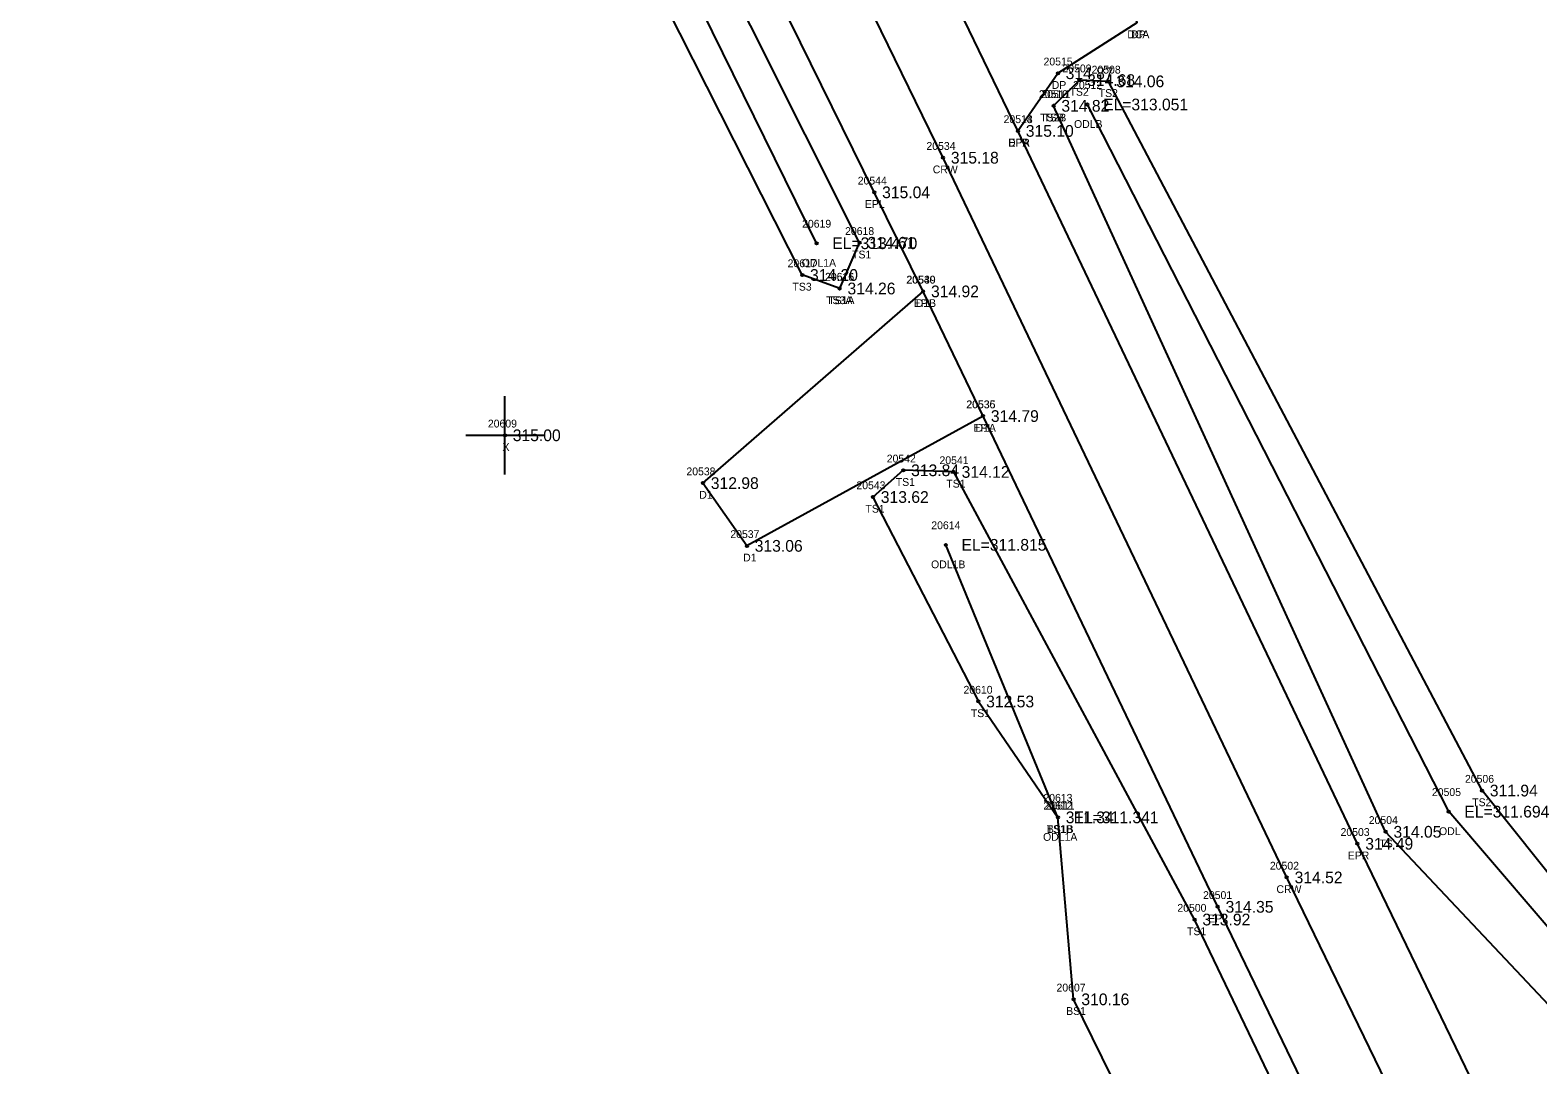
# Model space of a CAD drawing. Extents: x 1865771 to 1866867, y 910387 to 913581.
# Drawn here: x 1866027.9 to 1866220.8, y 911460.4 to 911592.8 of the extents above; entities that cross this region are included whole.
import ezdxf

# ---------------------------------------------------------------- set-up
doc = ezdxf.new("R2010")
doc.units = 0
for name, color, linetype in [('RD_DTM_BkLn1', 7, 'Continuous'), ('RD_DTM_BkLn2', 7, 'Continuous'), ('RD_DTM_BkLn_txCode', 7, 'Continuous'), ('RD_EX_Conc_txCode', 7, 'Continuous'), ('RD_EX_Driveway', 7, 'Continuous'), ('RD_EX_Driveway_txCode', 7, 'Continuous'), ('RD_EX_H2O', 7, 'Continuous'), ('RD_EX_H2O_txCode', 7, 'Continuous'), ('RD_EX_Misc', 7, 'Continuous'), ('RD_EX_Misc_txCode', 7, 'Continuous'), ('RD_EX_Road', 7, 'Continuous'), ('RD_EX_Road_txCode', 7, 'Continuous'), ('RD_EX_TX_Driveway_ELEV', 7, 'Continuous'), ('RD_EX_TX_H2O_ELEV', 7, 'Continuous'), ('RD_EX_TX_Misc_ELEV', 7, 'Continuous'), ('RD_EX_TX_Road_ELEV', 7, 'Continuous'), ('RD_HC_Survey_ELEV', 7, 'Continuous'), ('RD_HC_Survey_txCode', 7, 'Continuous'), ('RD_SMD_Locator', 7, 'Continuous')]:
    doc.layers.add(name, color=color, linetype=linetype)

msp = doc.modelspace()

# ---------------------------------------------------------------- linework, layer by layer
at = {"layer": 'RD_DTM_BkLn1'}
msp.add_lwpolyline([(1866367.09, 911115.22), (1866321.52, 911209.15), (1866277.71, 911299.75), (1866233.16, 911392.74), (1866188.7, 911484.36), (1866144.72, 911576.48), (1866098.88, 911670.46), (1866050.89, 911769.85), (1866036.73, 911799.27)], dxfattribs=at)
at = {"layer": 'RD_DTM_BkLn2'}
for points in [[(1866131.5, 911559.74), (1866126.7, 911561.47), (1866077.95, 911657.88), (1866039.91, 911695.55), (1866043.68, 911699.99)], [(1866131.5, 911559.74), (1866134.05, 911565.59), (1866085.26, 911662.93), (1866043.68, 911699.99)], [(1866228.56, 911467.21), (1866232.27, 911472.22), (1866213.68, 911495.48), (1866165.89, 911586.25), (1866162.16, 911586.41), (1866158.86, 911583.12)], [(1866228.56, 911467.21), (1866222.94, 911467.23), (1866201.35, 911490.2), (1866158.86, 911583.12)], [(1866355.6, 911109.43), (1866349.51, 911111.22), (1866350.92, 911120.01), (1866309.89, 911202.06), (1866265.74, 911294.86), (1866220.97, 911386.97), (1866176.9, 911478.97), (1866146.1, 911536.26), (1866139.64, 911536.47), (1866135.76, 911533.05), (1866149.24, 911506.88), (1866159.42, 911492.05)], [(1866341.34, 911101.29), (1866293.82, 911197.85), (1866256.26, 911274.61), (1866200.37, 911389.5), (1866161.42, 911468.76), (1866159.42, 911492.05)]]:
    msp.add_lwpolyline(points, dxfattribs=at)
at = {"layer": 'RD_EX_Driveway'}
for points in [[(1866154.31, 911579.91), (1866159.41, 911587.29), (1866169.57, 911593.77), (1866165.13, 911606.88), (1866152.14, 911603.8), (1866143.08, 911603.17)], [(1866149.84, 911543.41), (1866119.63, 911526.8), (1866114.01, 911534.83), (1866142.18, 911559.37)]]:
    msp.add_lwpolyline(points, dxfattribs=at)
at = {"layer": 'RD_EX_H2O'}
msp.add_line((1866159.42, 911492.05), (1866145.08, 911526.93), dxfattribs=at)
for points in [[(1866128.55, 911565.53), (1866081.91, 911660.36), (1866044.12, 911695.93)], [(1866226.46, 911472.93), (1866209.42, 911492.78), (1866163.2, 911583.29)]]:
    msp.add_lwpolyline(points, dxfattribs=at)
at = {"layer": 'RD_EX_Misc'}
for p, q in [((1866088.67, 911535.95), (1866088.67, 911545.95)), ((1866083.67, 911540.95), (1866093.67, 911540.95))]:
    msp.add_line(p, q, dxfattribs=at)
at = {"layer": 'RD_EX_Road'}
for points in [[(1866367.09, 911115.22), (1866376.17, 911119.76), (1866330.4, 911213.7), (1866286.92, 911304.16), (1866242.4, 911396.3), (1866197.74, 911488.67), (1866154.31, 911579.91), (1866143.08, 911603.17), (1866108.16, 911674.25), (1866059.64, 911774.84), (1866048.38, 911798.67), (1866045.99, 911803.62)], [(1866367.09, 911115.22), (1866357.99, 911110.97), (1866313.12, 911203.44), (1866268.86, 911295.9), (1866224.24, 911388.66), (1866179.87, 911480.6), (1866149.84, 911543.41), (1866142.18, 911559.37), (1866135.93, 911572.05), (1866096.83, 911651.51), (1866089.65, 911665.46), (1866062.87, 911720.39), (1866042.14, 911765.69), (1866027.93, 911795.04)]]:
    msp.add_lwpolyline(points, dxfattribs=at)
at = {"layer": 'RD_SMD_Locator'}
for centre in [(1866159.41, 911587.29), (1866162.16, 911586.41), (1866165.89, 911586.25), (1866158.86, 911583.12), (1866158.86, 911583.12), (1866163.2, 911583.29), (1866154.31, 911579.91), (1866154.31, 911579.91), (1866144.72, 911576.48), (1866135.93, 911572.05), (1866128.55, 911565.53), (1866134.05, 911565.59), (1866126.7, 911561.47), (1866131.5, 911559.74), (1866131.5, 911559.74), (1866142.18, 911559.37), (1866142.18, 911559.37), (1866149.84, 911543.41), (1866149.84, 911543.41), (1866088.67, 911540.95), (1866114.01, 911534.83), (1866139.64, 911536.47), (1866146.1, 911536.26), (1866135.76, 911533.05), (1866119.63, 911526.8), (1866145.08, 911526.93), (1866149.24, 911506.88), (1866213.68, 911495.48), (1866209.42, 911492.78), (1866159.42, 911492.05), (1866159.42, 911492.05), (1866159.42, 911492.05), (1866197.74, 911488.67), (1866201.35, 911490.2), (1866188.7, 911484.36), (1866176.9, 911478.97), (1866179.87, 911480.6), (1866161.42, 911468.76)]:
    msp.add_circle(centre, 0.15, dxfattribs=at)

# ---------------------------------------------------------------- texts
at = {"layer": 'RD_DTM_BkLn_txCode'}
for s, p in [('20509', (1866160, 911587.41)), ('20508', (1866163.73, 911587.25)), ('20510', (1866156.99, 911584.12)), ('20511', (1866157.31, 911584.12)), ('TS2', (1866160.91, 911584.41)), ('TS2', (1866164.64, 911584.25)), ('TS2B', (1866157.15, 911581.12)), ('TSB', (1866157.59, 911581.12)), ('20618', (1866132.19, 911566.59)), ('TS1', (1866133.09, 911563.59)), ('20617', (1866124.84, 911562.47)), ('TS3', (1866125.46, 911559.47)), ('20616', (1866129.62, 911560.74)), ('20615', (1866129.64, 911560.74)), ('TS3A', (1866129.77, 911557.74)), ('TS1A', (1866130.05, 911557.74)), ('20542', (1866137.52, 911537.47)), ('20541', (1866144.27, 911537.26)), ('20543', (1866133.64, 911534.05)), ('TS1', (1866138.68, 911534.47)), ('TS1', (1866145.14, 911534.26)), ('TS1', (1866134.8, 911531.05)), ('20610', (1866147.34, 911507.88)), ('TS1', (1866148.28, 911504.88)), ('20506', (1866211.5, 911496.48)), ('TS2', (1866212.43, 911493.48)), ('20612', (1866157.56, 911493.05)), ('20611', (1866157.84, 911493.05)), ('TS1B', (1866157.98, 911490.05)), ('BS1B', (1866158, 911490.05)), ('20504', (1866199.19, 911491.2)), ('TS', (1866200.55, 911488.2)), ('20500', (1866174.7, 911479.97)), ('TS1', (1866175.94, 911476.97)), ('20607', (1866159.24, 911469.76)), ('BS1', (1866160.48, 911466.76))]:
    msp.add_text(s, height=1, dxfattribs=at).set_placement(p)
at = {"layer": 'RD_EX_Conc_txCode'}
msp.add_text('DCA', height=1, dxfattribs=at).set_placement((1866168.3, 911591.77))
at = {"layer": 'RD_EX_Driveway_txCode'}
for s, p in [('DP', (1866168.79, 911591.77)), ('20515', (1866157.58, 911588.29)), ('DP', (1866158.63, 911585.29)), ('20514', (1866152.47, 911580.91)), ('DPA', (1866153.04, 911577.91)), ('20539', (1866140.06, 911560.37)), ('D1B', (1866141.23, 911557.37)), ('20536', (1866147.69, 911544.41)), ('D1A', (1866148.88, 911541.41)), ('20538', (1866111.89, 911535.83)), ('D1', (1866113.53, 911532.83)), ('20537', (1866117.51, 911527.8)), ('D1', (1866119.15, 911524.8))]:
    msp.add_text(s, height=1, dxfattribs=at).set_placement(p)
at = {"layer": 'RD_EX_H2O_txCode'}
for s, p in [('20512', (1866161.36, 911585.29)), ('ODLB', (1866161.48, 911580.29)), ('20619', (1866126.69, 911567.53)), ('ODL1A', (1866126.65, 911562.53)), ('20614', (1866143.22, 911528.93)), ('ODL1B', (1866143.19, 911523.93)), ('20613', (1866157.56, 911494.05)), ('20505', (1866207.27, 911494.78)), ('ODL', (1866208.18, 911489.78)), ('ODL1A', (1866157.52, 911489.05))]:
    msp.add_text(s, height=1, dxfattribs=at).set_placement(p)
at = {"layer": 'RD_EX_Misc_txCode'}
for s, p in [('20609', (1866086.49, 911541.95)), ('X', (1866088.36, 911538.95))]:
    msp.add_text(s, height=1, dxfattribs=at).set_placement(p)
at = {"layer": 'RD_EX_Road_txCode'}
for s, p in [('20513', (1866152.47, 911580.91)), ('EPR', (1866153.08, 911577.91)), ('20544', (1866133.81, 911573.05)), ('EPL', (1866134.72, 911570.05)), ('20540', (1866140.02, 911560.37)), ('EPL', (1866140.97, 911557.37)), ('20535', (1866147.72, 911544.41)), ('EPL', (1866148.63, 911541.41)), ('20503', (1866195.58, 911489.67)), ('EPR', (1866196.51, 911486.67)), ('20501', (1866177.99, 911481.6)), ('EPL', (1866178.66, 911478.6))]:
    msp.add_text(s, height=1, dxfattribs=at).set_placement(p)
at = {"layer": 'RD_EX_TX_Driveway_ELEV'}
for s, p in [('314.87', (1866160.41, 911586.54)), ('315.10', (1866155.31, 911579.16)), ('314.92', (1866143.18, 911558.62)), ('314.79', (1866150.84, 911542.66)), ('312.98', (1866115.01, 911534.08)), ('313.06', (1866120.63, 911526.05))]:
    msp.add_text(s, height=1.5, dxfattribs=at).set_placement(p)
at = {"layer": 'RD_EX_TX_H2O_ELEV'}
for s, p in [('EL=313.051', (1866165.2, 911582.54)), ('EL=313.470', (1866130.55, 911564.78)), ('EL=311.815', (1866147.08, 911526.18)), ('EL=311.341', (1866161.42, 911491.3)), ('EL=311.694', (1866211.42, 911492.03))]:
    msp.add_text(s, height=1.5, dxfattribs=at).set_placement(p)
at = {"layer": 'RD_EX_TX_Misc_ELEV'}
for s, p in [('314.68', (1866163.16, 911585.66)), ('314.06', (1866166.89, 911585.5)), ('314.82', (1866159.86, 911582.37)), ('314.82', (1866159.86, 911582.37)), ('314.61', (1866135.05, 911564.84)), ('314.20', (1866127.7, 911560.72)), ('314.26', (1866132.5, 911558.99)), ('314.26', (1866132.5, 911558.99)), ('315.00', (1866089.67, 911540.2)), ('313.84', (1866140.64, 911535.72)), ('314.12', (1866147.1, 911535.51)), ('313.62', (1866136.76, 911532.3)), ('312.53', (1866150.24, 911506.13)), ('311.94', (1866214.68, 911494.73)), ('311.34', (1866160.42, 911491.3)), ('311.34', (1866160.42, 911491.3)), ('314.05', (1866202.35, 911489.45)), ('313.92', (1866177.9, 911478.22)), ('310.16', (1866162.42, 911468.01))]:
    msp.add_text(s, height=1.5, dxfattribs=at).set_placement(p)
at = {"layer": 'RD_EX_TX_Road_ELEV'}
for s, p in [('315.10', (1866155.31, 911579.16)), ('315.04', (1866136.93, 911571.3)), ('314.92', (1866143.18, 911558.62)), ('314.79', (1866150.84, 911542.66)), ('314.49', (1866198.74, 911487.92)), ('314.35', (1866180.87, 911479.85))]:
    msp.add_text(s, height=1.5, dxfattribs=at).set_placement(p)
at = {"layer": 'RD_HC_Survey_ELEV'}
for s, p in [('315.18', (1866145.72, 911575.73)), ('314.52', (1866189.7, 911483.61))]:
    msp.add_text(s, height=1.5, dxfattribs=at).set_placement(p)
at = {"layer": 'RD_HC_Survey_txCode'}
for s, p in [('20534', (1866142.6, 911577.48)), ('CRW', (1866143.41, 911574.48)), ('20502', (1866186.54, 911485.36)), ('CRW', (1866187.38, 911482.36))]:
    msp.add_text(s, height=1, dxfattribs=at).set_placement(p)

doc.saveas('drawing.dxf')
